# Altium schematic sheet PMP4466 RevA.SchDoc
size 431 x 279 mm; Date: Not shown in title block; ApprovedBy: Not shown in title block; CheckedBy: Not shown in title block; Author: Not shown in title block; CompanyName: Not shown in title block; Engineer: Jackyzhang; Organization: Not shown in title block; Address1: Not shown in title block; Address2: Not shown in title block; Address3: Not shown in title block; Address4: Not shown in title block; DocumentNumber: 1; Revision: A; SheetNumber: 1; SheetTotal: 1; PageSetup: Record=PageOptions¦CenterHorizontal=True¦CenterVertical=True¦PrintScale=1.00¦XCorrection=1.00¦YCorrection=1.00¦PrintKind=0¦BorderSize=5000000¦LeftOffset=0¦BottomOffset=0¦Orientation=2¦PaperLength=1000¦PaperWidth=1000¦Scale=100¦PaperSource=15¦PrintQuality=600¦MediaType=1¦DitherType=10¦PaperKind=Letter¦PrintScaleMode=1
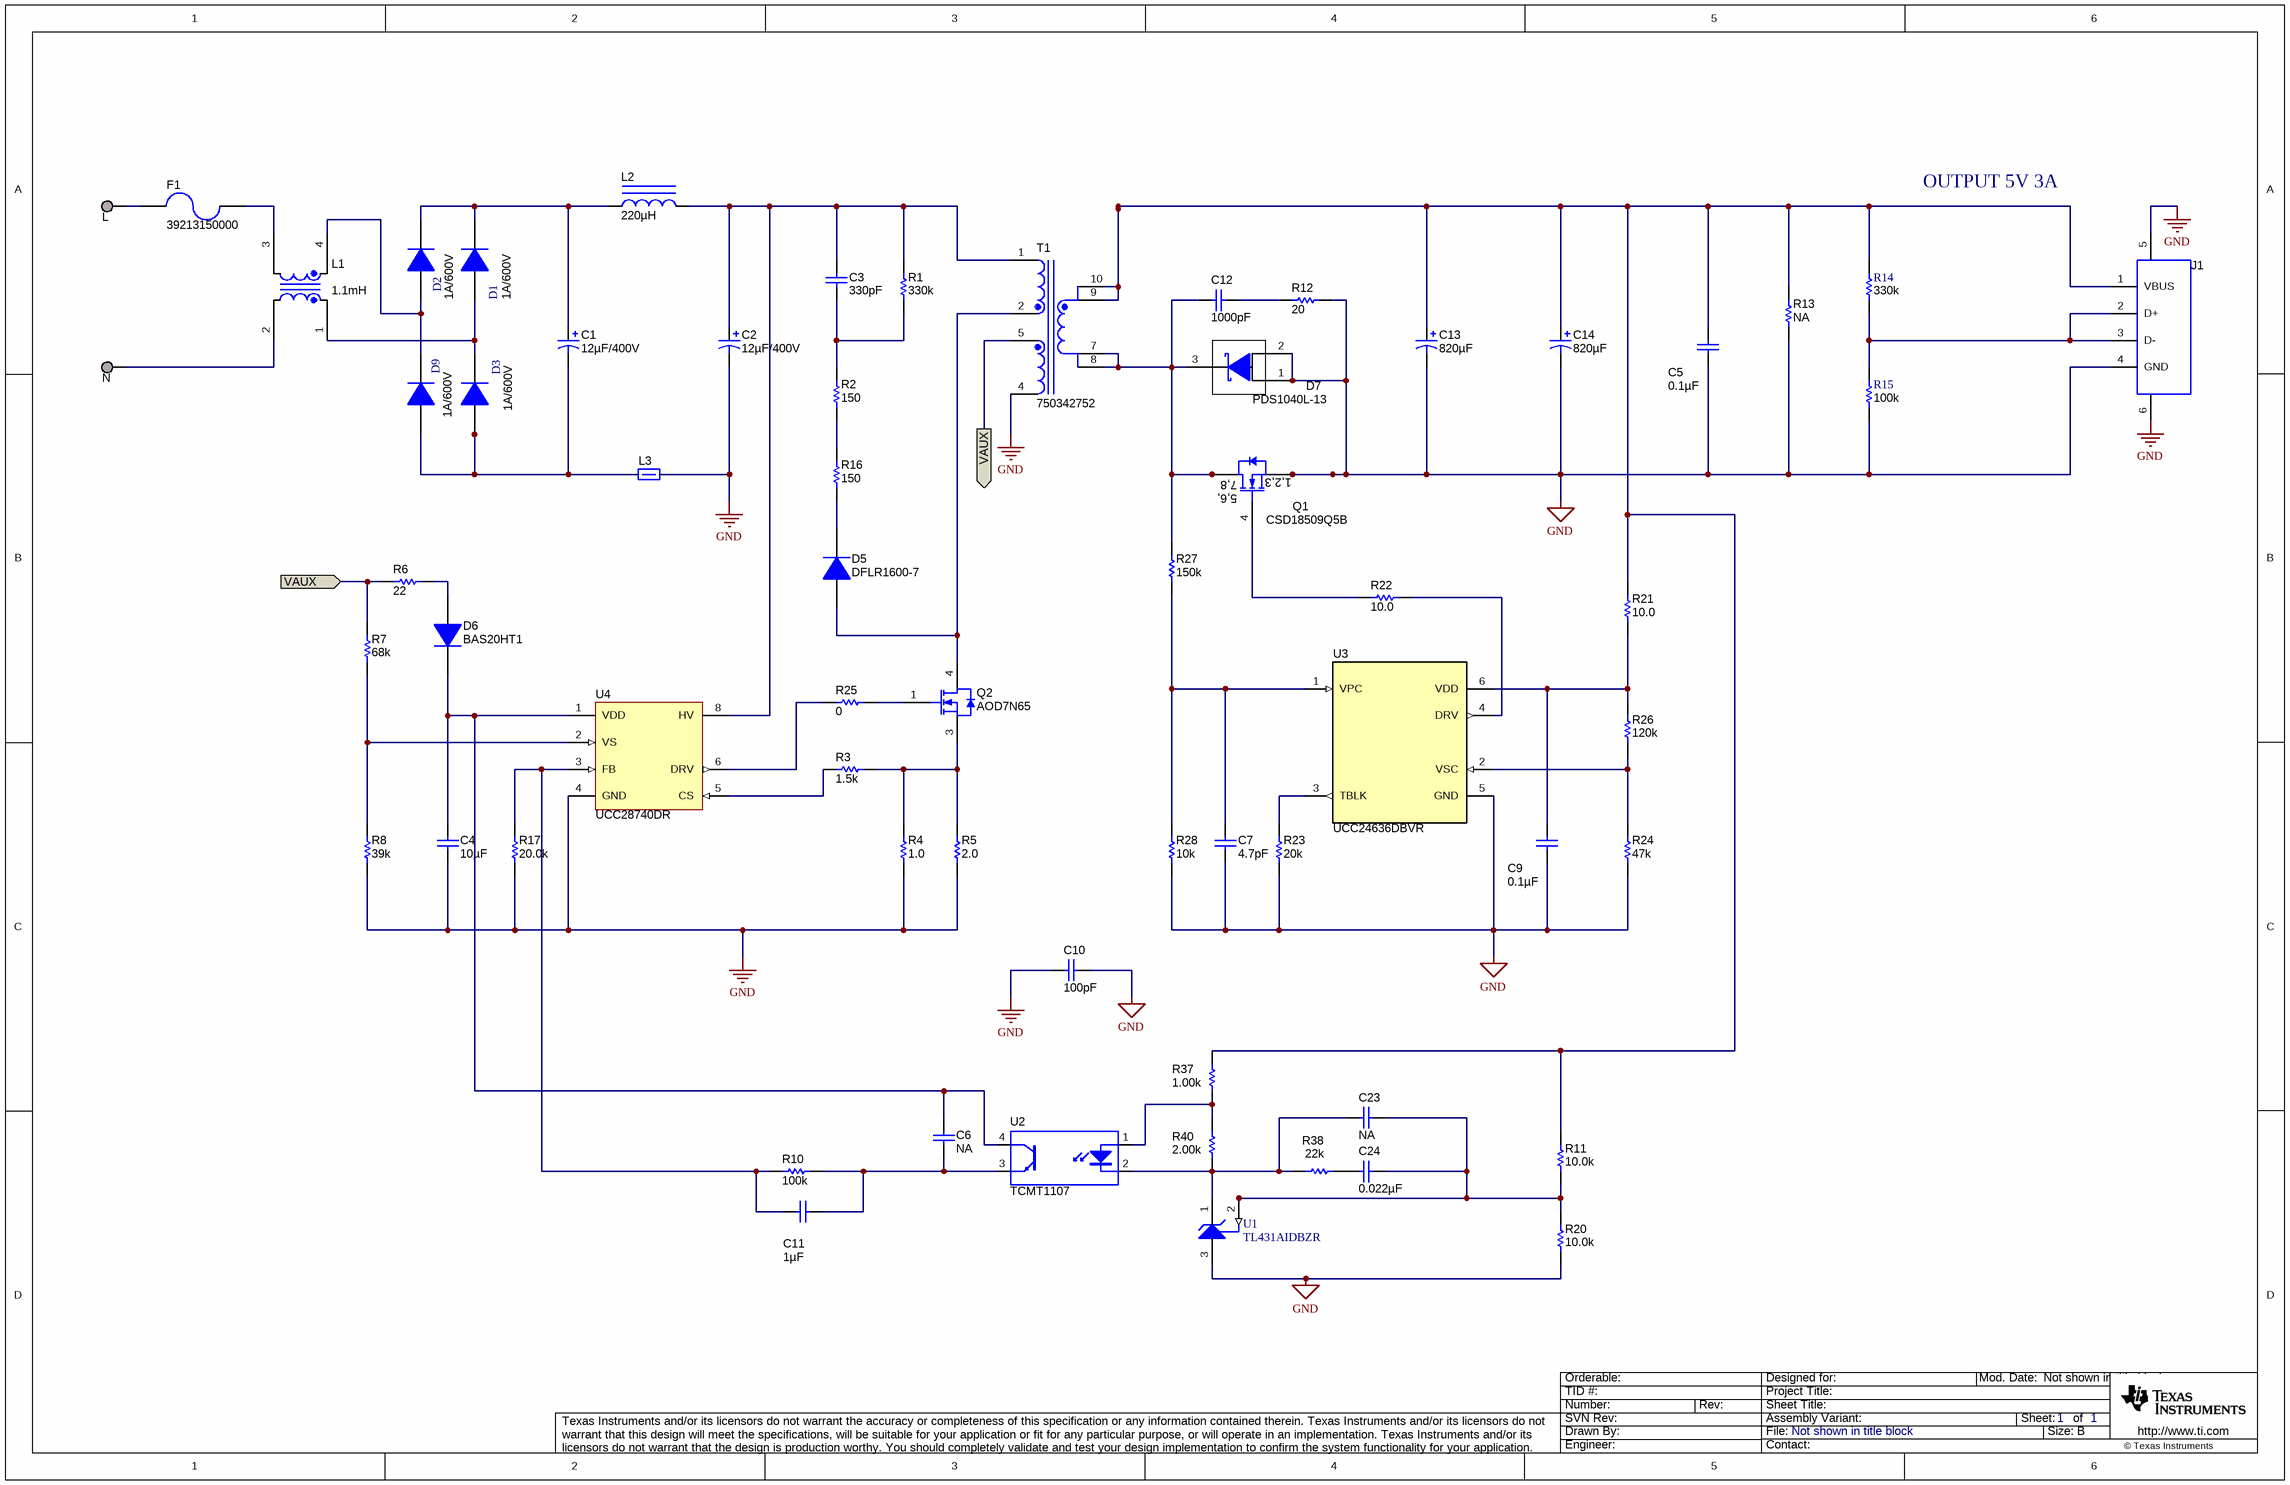
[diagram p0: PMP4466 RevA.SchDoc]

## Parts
C1  ValueDisplayed: 12µF/400V  [CAPPR5-10X20]  (hidden comment: EEUED2G100)
C2  ValueDisplayed: 12µF/400V  [CAPPR5-10X20]  (hidden comment: EEUED2G100)
C3  ValueDisplayed: 330pF  [1206]  (hidden comment: GRM31A5C2J331JW01D)
C4  ValueDisplayed: 10µF  [1206_190]  (hidden comment: GMK316AB7106KL-TR)
C5  ValueDisplayed: 0.1µF  [0603]  (hidden comment: C1608X7R1E104K)
C6  ValueDisplayed: NA  [0603]  (hidden comment: C0603X223K5RACTU)
C7  ValueDisplayed: 4.7pF  [0603]  (hidden comment: 06035A150JAT2A)
C9  ValueDisplayed: 0.1µF  [0603]  (hidden comment: C1608X7R1E104K)
C10  ValueDisplayed: 100pF  [CAPRD1000W60D1000H1400]  (hidden comment: DE1B3KX101K)
C11  ValueDisplayed: 1µF  [0603_095]  (hidden comment: C0603C105K3RACTU)
C12  ValueDisplayed: 1000pF  [0603]  (hidden comment: 06035A102KAT2A)
C13  ValueDisplayed: 820µF  [CAPSMT_62_J80]  (hidden comment: APXE6R3ARA821MJ80G)
C14  ValueDisplayed: 820µF  [CAPSMT_62_J80]  (hidden comment: APXE6R3ARA821MJ80G)
C23  ValueDisplayed: NA  [0603]  (hidden comment: C0603X223K5RACTU)
C24  ValueDisplayed: 0.022µF  [0603]  (hidden comment: C0603X223K5RACTU)
D1  1A/600V  [powerDI123]
D2  1A/600V  [powerDI123]
D3  1A/600V  [powerDI123]
D5  DFLR1600-7  [powerDI123]
D6  BAS20HT1  [sod-323]
D7  PDS1040L-13  [PowerDI5]
D9  1A/600V  [powerDI123]
F1  39213150000  [FUSE_392]
J1  896-43-004-00-000000  [USB-BYDAAA]  (value not drawn)
L  TESTPOINT  [Keystone_5019]  (value not drawn)  (no BOM)
L1  ValueDisplayed: 1.1mH  [IND_RLTI-1081]  (hidden comment: 131205000043)
L2  ValueDisplayed: 220µH  [WE-TI_5075]  (hidden comment: 7447462221)
L3  HF70ACC322513  [1206]  (value not drawn)
N  TESTPOINT  [Keystone_5019]  (value not drawn)  (no BOM)
Q1  CSD18509Q5B  [TRANS_NexFET_Q5B]
Q2  AOD7N65  [DPAK]
R1  ValueDisplayed: 330k  [1206]  (hidden comment: CRCW1206330KJNEA)
R2  ValueDisplayed: 150  [1206]  (hidden comment: CRCW1206150RJNEA)
R3  ValueDisplayed: 1.5k  [0603]  (hidden comment: CRCW06031K50JNEA)
R4  ValueDisplayed: 1.0  [1206]  (hidden comment: CRCW12061R00JNEA)
R5  ValueDisplayed: 2.0  [1206]  (hidden comment: CRCW12062R00JNEA)
R6  ValueDisplayed: 22  [0603]  (hidden comment: CRCW060322R0JNEA)
R7  ValueDisplayed: 68k  [0603]  (hidden comment: CRCW060368K0JNEA)
R8  ValueDisplayed: 39k  [0603]  (hidden comment: CRCW060339K0JNEA)
R10  ValueDisplayed: 100k  [0603]  (hidden comment: CRCW0603100KFKEA)
R11  ValueDisplayed: 10.0k  [0603]  (hidden comment: CRCW060310K0FKEA)
R12  ValueDisplayed: 20  [0805_HV]  (hidden comment: CRCW080520R0JNEA)
R13  ValueDisplayed: NA  [0603]  (hidden comment: Res2)
R14  ValueDisplayed: 330k  [0603]  (hidden comment: RC0603FR-07330KL)
R15  ValueDisplayed: 100k  [0603]  (hidden comment: RC0603FR-07100KL)
R16  ValueDisplayed: 150  [1206]  (hidden comment: CRCW1206150RJNEA)
R17  ValueDisplayed: 20.0k  [0603]  (hidden comment: CRCW060320K0FKEA)
R20  ValueDisplayed: 10.0k  [0603]  (hidden comment: CRCW060310K0FKEA)
R21  ValueDisplayed: 10.0  [0603]  (hidden comment: CRCW060310R0FKEA)
R22  ValueDisplayed: 10.0  [0603]  (hidden comment: CRCW060310R0FKEA)
R23  ValueDisplayed: 20k  [0603]  (hidden comment: CRCW060313K0JNEA)
R24  ValueDisplayed: 47k  [0603]  (hidden comment: CRCW060347K0JNEA)
R25  ValueDisplayed: 0  [0603]  (hidden comment: CRCW06030000Z0EA)
R26  ValueDisplayed: 120k  [0603]  (hidden comment: CRCW060391K0JNEA)
R27  ValueDisplayed: 150k  [0603]  (hidden comment: CRCW0603150KFKEA)
R28  ValueDisplayed: 10k  [0603]  (hidden comment: CRCW060310K0JNEA)
R37  ValueDisplayed: 1.00k  [0603]  (hidden comment: CRCW06031K00FKEA)
R38  ValueDisplayed: 22k  [0603]  (hidden comment: CRCW060322K0JNEA)
R40  ValueDisplayed: 2.00k  [0603]  (hidden comment: CRCW06032K00FKEA)
T1  750342752  [Wurth_750342752]
U1  TL431AIDBZR  [DBZ0003A_N]
U2  TCMT1107  [SOP-4]
U3  UCC24636DBVR  [DBV0006A_N]
U4  UCC28740DR  [D0007A_N]

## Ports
VAUX (in), VAUX (out)

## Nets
GND: C2.2(-) C4.2 C5.2 C7.2 C9.2 C10.1 C10.2 C13.2(-) C14.2(-) D7.1(A) D7.2(A) J1.4(GND) J1.5(Shield) J1.6(Shield) L3.2 Q1.1(S) Q1.2(S) Q1.3(S) R4.1 R5.1 R8.1 R12.2 R13.1 R15.1 R17.1 R20.1 R23.1 R24.1 R28.1 T1.4 U1.3(ANODE) U3.5(GND) U4.4(GND)
VAUX: R6.2 R7.2 T1.5 ; port VAUX
NetC1_1: C1.1(+) D1.1(K) D2.1(K) L2.1
NetC1_2: C1.2(-) D3.2(A) D9.2(A) L3.1
NetC2_1: C2.1(+) C3.1 L2.2 R1.2 T1.1 U4.8(HV)
NetC3_2: C3.2 R1.1 R2.2
NetC4_1: C4.1 C6.1 D6.1(K) U2.4(C) U4.1(VDD)
NetC5_1: C5.1 C13.1(+) C14.1(+) J1.1(VBUS) R11.2 R13.2 R14.2 R21.2 R37.2 T1.9 T1.10
NetC6_2: C6.2 C11.1 R10.2 U2.3(E)
NetC7_1: C7.1 R27.1 R28.2 U3.1(VPC)
NetC9_1: C9.1 R21.1 R26.2 U3.6(VDD)
NetC11_2: C11.2 R10.1 R17.2 U4.3(FB)
NetC12_1: C12.1 R12.1
NetC12_2: C12.2 D7.3(K) Q1.5(D) Q1.6(D) Q1.7(D) Q1.8(D) R27.2 T1.7 T1.8
NetC23_1: C23.1 C24.1 R11.1 R20.2 U1.2(REF)
NetC23_2: C23.2 R38.1 R40.1 U1.1(CATHODE) U2.2(K)
NetC24_2: C24.2 R38.2
NetD1_2: D1.2(A) D3.1(K) L1.1
NetD2_2: D2.2(A) D9.1(K) L1.4
NetD5_1: D5.1(K) R16.1
NetD5_2: D5.2(A) Q2.4(D) T1.2
NetD6_2: D6.2(A) R6.1
NetF1_1: F1.1 L1.3
NetF1_2: F1.2 L.1
NetJ1_2: J1.2(D+) J1.3(D-) R14.1 R15.2
NetL1_2: L1.2 N.1
NetQ1_4: Q1.4(G) R22.1
NetQ2_1: Q2.1(G) R25.2
NetQ2_3: Q2.3(S) R3.2 R4.2 R5.2
NetR2_1: R2.1 R16.2
NetR3_1: R3.1 U4.5(CS)
NetR7_1: R7.1 R8.2 U4.2(VS)
NetR22_2: R22.2 U3.4(DRV)
NetR23_2: R23.2 U3.3(TBLK)
NetR24_2: R24.2 R26.1 U3.2(VSC)
NetR25_1: R25.1 U4.6(DRV)
NetR37_1: R37.1 R40.2 U2.1(A)

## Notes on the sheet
- OUTPUT 5V 3A

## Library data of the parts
C1 C2 = EEUED2G100: CAP, AL, 10 µF, 400 V, +/- 20%, 2.864788 ohm, TH; Manufacturer: Panasonic; Polarized: Y; CompType: Capacitor; Value: 12uF; U/M: EA; Cap_F: 0.00001; Tolerance_%: 20; VDC_V: 400; Value2: 400V; IRMS_A: 0.3; TaMin_C: -25; TaMax_C: 105
C3 = GRM31A5C2J331JW01D: CAP, CERM, 330 pF, 630 V, +/- 5%, C0G/NP0, 1206; Manufacturer: MuRata; Polarized: N; CompType: Capacitor; Value: 330pF; U/M: EA; Cap_F: 0.00000000033; Tolerance_%: 5; Value1: Unknown; VDC_V: 630; Value2: 630V; TaMin_C: -55; TaMax_C: 125
C4 = GMK316AB7106KL-TR: CAP, CERM, 10 µF, 35 V, +/- 10%, X7R, 1206_190; Manufacturer: Taiyo Yuden; Polarized: N; CompType: Capacitor; Value: 10uF; U/M: EA; Cap_F: 0.00001; Tolerance_%: 10; Value1: Unknown; VDC_V: 35; Value2: 35V; TaMin_C: -55; TaMax_C: 125; Cap_Case: 1206
C5 C9 = C1608X7R1E104K: CAP, CERM, 0.1 µF, 25 V, +/- 10%, X7R, 0603; Manufacturer: TDK; Polarized: N; CompType: Capacitor; Value: 0.1uF; U/M: EA; Cap_F: 0.0000001; Tolerance_%: 10; ESR_ohm: 0.017; Value1: 0.017 ohm; VDC_V: 25; Value2: 25V; TaMin_C: -55; TaMax_C: 125
C6 C23 C24 = C0603X223K5RACTU: CAP, CERM, 0.022 µF, 50 V, +/- 10%, X7R, 0603; Manufacturer: Kemet; Polarized: N; CompType: Capacitor; Value: 0.022uF; U/M: EA; Cap_F: 0.000000022; Tolerance_%: 10; Value1: Unknown; VDC_V: 50; Value2: 50V; TaMin_C: -55; TaMax_C: 125
C7 = 06035A150JAT2A: CAP, CERM, 15 pF, 50 V, +/- 5%, C0G/NP0, 0603; Manufacturer: AVX; Polarized: N; CompType: Capacitor; Value: 15pF; U/M: EA; Cap_F: 0.000000000015; Tolerance_%: 5; ESR_ohm: 0.32; Value1: 0.32 ohm; VDC_V: 50; Value2: 50V; TaMin_C: -55; TaMax_C: 125
C10 = DE1E3KX222MA5BA01: CAP, CERM, 100 pF, 250 V, +/- 20%, E, Disc 10x8mm; Manufacturer: MuRata; Polarized: N; CompType: Capacitor; Value: 100pF; U/M: EA; Cap_F: 0.0000000022; Tolerance_%: 20; Value1: Unknown; VDC_V: 250; Value2: 250V; TaMin_C: -25; TaMax_C: 85
C11 = C0603C105K3RACTU: CAP, CERM, 1 µF, 25 V, +/- 10%, X7R, 0603_095; Manufacturer: Kemet; Polarized: N; CompType: Capacitor; Value: 1uF; U/M: EA; Cap_F: 0.000001; Tolerance_%: 10; Value1: Unknown; VDC_V: 25; Value2: 25V; TaMin_C: -55; TaMax_C: 125; Cap_Case: 0603
C12 = 06035A102KAT2A: CAP, CERM, 1000 pF, 50 V, +/- 10%, C0G/NP0, 0603; Manufacturer: AVX; Polarized: N; CompType: Capacitor; Value: 1000pF; U/M: EA; Cap_F: 0.000000001; Tolerance_%: 10; ESR_ohm: 0.048; Value1: 0.048 ohm; VDC_V: 50; Value2: 50V; TaMin_C: -55; TaMax_C: 125
C13 C14 = APXE6R3ARA821MJ80G: CAP, AL, 820 µF, 6.3 V, +/- 20%, 0.014 ohm, SMD; Manufacturer: Chemi-Con; Polarized: Y; CompType: Capacitor; Value: 820uF; U/M: EA; Cap_F: 0.00082; Tolerance_%: 20; VDC_V: 6.3; Value2: 6.3V; ESR_ohm: 0.014; IRMS_A: 4.3; TaMin_C: -55; TaMax_C: 105; Cap_Case: J80; AEC Category: Q200
D1-D3 D9 = DFLR1600-7: Diode, Standard Recovery Rectifier, 600 V, 1 A, PowerDI123; Manufacturer: Diodes Inc.; U/M: EA; Vf_V: 1.1; Value: 600V; Value1: 1A; Value2: 1.1V; Io_A: 1; Vr_V: 600; TJmax_C: 150; AEC Category: Q101
D5 = DFLR1600-7: Diode, Standard Recovery Rectifier, 600 V, 1 A, PowerDI123; Manufacturer: Diodes Inc.; U/M: EA; Vf_V: 1.1; Value: 600V; Value1: 1A; Value2: 1.1V; Io_A: 1; Vr_V: 600; TJmax_C: 150
D6 = BAV20WS-TP: Diode, P-N, 150 V, 0.2 A, SOD-323; Manufacturer: ON Semiconductor; U/M: EA; Vf_V: 1.25; Value: 150V; Value1: 0.2A; Value2: 1.25V; Io_A: 0.2; Vr_V: 150
D7 = PDS1040L-13: Diode, Schottky, 40 V, 10 A, PowerDI5; Manufacturer: Diodes Inc.; U/M: EA; Vf_V: 0.49; Value: 40V; Value1: 10A; Value2: 0.49V; Io_A: 10; Vr_V: 40; TJmax_C: 150; RJC_CperW: 85
F1 = 39213150000: Fuse, 3.15 A, 250 V, TH; Manufacturer: Littelfuse; U/M: EA; OpeningTime_200%_max: 120; VDC_V: 250; Irating_A: 3.15; Vdrop: 0.08; Soldering_Wave_MaxTemp_C: 260; Soldering_Wave_MaxTime_s: 5
J1 = 896-43-004-00-000000: Connector, Receptacle, USB TYPE A, R/A, Top Mount SMT; Manufacturer: Mill-Max; SymbolCreator: a0412235; Pitch_mm: 2; Gender: Female; Shrouded: N; Row_Count: 1; ContactFinish: Gold; Voltage_V: 30
L N = 5019: Test Point, Miniature, SMT; Manufacturer: Keystone; CompType: Test Point Loop; U/M: EA
L1 = RLTI-1081: Coupled inductor, 1.1 mH, TH; Manufacturer: Dongguan Yuefeng; SymbolCreator: a0412235; Ind_H: 806.0E-6; DCR_ohm: 0.27; Tolerance_%: 25; Value: 1.1mH
L2 = 7447462221: Inductor, Unshielded Drum Core, Ferrite, 220 µH, 0.5 A, 0.96 ohm, TH; Manufacturer: Wurth Elektronik; Value: 220uH; Ind_H: 220.0E-6; Imax_A: 0.5; Irms: 0.5A @ 40C rise; Isat: 0.5A @ 10% inductance drop; DCR_ohm: 0.96; Value2: 0.5A; AEC Category: Q200
L3 = HZ1206E152R-10: Ferrite Bead, 950 ohm @ 100 MHz, 0.5 A, 1206; Manufacturer: TDK; Imax_A: 0.5; DCR_ohm: 0.3
Q1 = CSD18509Q5B: MOSFET, N-CH, 40 V, 38 A, SON 5x6mm; Manufacturer: Texas Instruments; Alternate Manufacturer: None; U/M: EA; ChType: N; Value: 40V; VdsMax_V: 40; Value1: 0.0017 ohm; Rdson45_ohm: 0.0017; Value2: 150 nC; QgTyp_nC: 150; Vgs_V: 20; IdsMax_A: 38
Q2 = AOD7N65: MOSFET, N-CH, 650 V, 7 A, DPAK; Manufacturer: AOS; Alternate Manufacturer: None; U/M: EA; ChType: N; Value: 650V; VdsMax_V: 650; Value1: ? ohm; Value2: 19.6 nC; QgTyp_nC: 19.6; Vgs_V: 30; IdsMax_A: 7
R1 = CRCW1206330KJNEA: RES, 330 k, 5%, 0.25 W, 1206; Manufacturer: Vishay-Dale; CompType: Resistor; Value: 330k; Res_ohm: 330000; Tolerance_%: 5; Power_W: 0.25; Value2: 0.25W; VDC_V: 200; TempCo: 200 ppm/C; EIA_Code: E24; U/M: EA
R2 R16 = CRCW1206150RJNEA: RES, 150, 5%, 0.25 W, 1206; Manufacturer: Vishay-Dale; CompType: Resistor; Value: 150; Value_Code: 150R; Tolerance_%: 5; Power_W: 0.25; Value2: 0.25W; VDC_V: 200; TempCo: 200 ppm/C; EIA_Code: E24; U/M: EA
R3 = CRCW06031K50JNEA: RES, 1.5 k, 5%, 0.1 W, 0603; Manufacturer: Vishay-Dale; CompType: Resistor; Value: 1.5k; Res_ohm: 1500; Value_Code: 1k50; Tolerance_%: 5; Power_W: 0.1; Value2: 0.1W; VDC_V: 75; TempCo: 200 ppm/C; EIA_Code: E24; U/M: EA
R4 = CRCW12061R00JNEA: RES, 1.0, 5%, 0.25 W, 1206; Manufacturer: Vishay-Dale; CompType: Resistor; Value: 1.0; Res_ohm: 1; Value_Code: 1R00; Tolerance_%: 5; Power_W: 0.25; Value2: 0.25W; VDC_V: 200; TempCo: 200 ppm/C; EIA_Code: E24; U/M: EA
R5 = CRCW12062R00JNEA: RES, 2.0, 5%, 0.25 W, 1206; Manufacturer: Vishay-Dale; CompType: Resistor; Value: 2.0; Res_ohm: 2; Value_Code: 2R00; Tolerance_%: 5; Power_W: 0.25; Value2: 0.25W; VDC_V: 200; TempCo: 200 ppm/C; EIA_Code: E24; U/M: EA
R6 = CRCW060322R0JNEA: RES, 22, 5%, 0.1 W, 0603; Manufacturer: Vishay-Dale; CompType: Resistor; Value: 22; Value_Code: 22R0; Tolerance_%: 5; Power_W: 0.1; Value2: 0.1W; VDC_V: 75; TempCo: 200 ppm/C; EIA_Code: E24; U/M: EA
R7 = CRCW060368K0JNEA: RES, 68 k, 5%, 0.1 W, 0603; Manufacturer: Vishay-Dale; CompType: Resistor; Value: 68k; Res_ohm: 68000; Value_Code: 68k0; Tolerance_%: 5; Power_W: 0.1; Value2: 0.1W; VDC_V: 75; TempCo: 200 ppm/C; EIA_Code: E24; U/M: EA
R8 = CRCW060339K0JNEA: RES, 39 k, 5%, 0.1 W, 0603; Manufacturer: Vishay-Dale; CompType: Resistor; Value: 39k; Res_ohm: 39000; Value_Code: 39k0; Tolerance_%: 5; Power_W: 0.1; Value2: 0.1W; VDC_V: 75; TempCo: 200 ppm/C; EIA_Code: E24; U/M: EA
R10 = CRCW0603100KFKEA: RES, 100 k, 1%, 0.1 W, 0603; Manufacturer: Vishay-Dale; CompType: Resistor; Value: 100k; Res_ohm: 100000; Tolerance_%: 1; Power_W: 0.1; Value2: 0.1W; VDC_V: 75; TempCo: 100 ppm/C; EIA_Code: E96; U/M: EA
R11 R20 = CRCW060310K0FKEA: RES, 10.0 k, 1%, 0.1 W, 0603; Manufacturer: Vishay-Dale; CompType: Resistor; Value: 10.0k; Res_ohm: 10000; Value_Code: 10k0; Tolerance_%: 1; Power_W: 0.1; Value2: 0.1W; VDC_V: 75; TempCo: 100 ppm/C; EIA_Code: E96; U/M: EA
R12 = CRCW080520R0JNEA: RES, 20, 5%, 0.125 W, 0805; Manufacturer: Vishay-Dale; CompType: Resistor; Value: 20; Value_Code: 20R0; Tolerance_%: 5; Power_W: 0.125; Value2: 0.125W; VDC_V: 150; TempCo: 200 ppm/C; EIA_Code: E24; U/M: EA
R13 = RC0603FR-071K3L: RES, 1.30 k, 1%, 0.1 W, 0603; Manufacturer: Yageo America; CompType: Resistor; Value: 1.30k; Res_ohm: 1300; Value_Code: 1k30; Tolerance_%: 1; Power_W: 0.1; Value2: 0.1W; VDC_V: 150; TempCo: 200 ppm/C; EIA_Code: E96; U/M: EA; AEC Category: Q200
R14 = RC0603FR-07330KL: RES, 330 k, 1%, 0.1 W, 0603; Manufacturer: Yageo America; Value: 330k; CompType: Resistor; Res_ohm: 330000; Tolerance_%: 1; Power_W: 0.1; Value2: 0.1W; VDC_V: 150; TempCo: 200 ppm/C; U/M: EA; AEC Category: Q200
R15 = RC0603FR-07100KL: RES, 100 k, 1%, 0.1 W, 0603; Manufacturer: Yageo America; Value: 100k; CompType: Resistor; Res_ohm: 100000; Tolerance_%: 1; Power_W: 0.1; Value2: 0.1W; VDC_V: 150; TempCo: 200 ppm/C; EIA_Code: E96; U/M: EA; AEC Category: Q200
R17 = CRCW060320K0FKEA: RES, 20.0 k, 1%, 0.1 W, 0603; Manufacturer: Vishay-Dale; CompType: Resistor; Value: 20.0k; Res_ohm: 20000; Value_Code: 20k0; Tolerance_%: 1; Power_W: 0.1; Value2: 0.1W; VDC_V: 75; TempCo: 100 ppm/C; EIA_Code: E96; U/M: EA
R21 R22 = CRCW060310R0FKEA: RES, 10.0, 1%, 0.1 W, 0603; Manufacturer: Vishay-Dale; CompType: Resistor; Value: 10.0; Res_ohm: 10; Value_Code: 10R0; Tolerance_%: 1; Power_W: 0.1; Value2: 0.1W; VDC_V: 75; TempCo: 100 ppm/C; EIA_Code: E96; U/M: EA; AEC Category: Q200
R23 = CRCW060313K0JNEA: RES, 13 k, 5%, 0.1 W, 0603; Manufacturer: Vishay-Dale; CompType: Resistor; Value: 13k; Res_ohm: 13000; Value_Code: 13k0; Tolerance_%: 5; Power_W: 0.1; Value2: 0.1W; VDC_V: 75; TempCo: 200 ppm/C; EIA_Code: E24; U/M: EA
R24 = CRCW060347K0JNEA: RES, 47 k, 5%, 0.1 W, 0603; Manufacturer: Vishay-Dale; CompType: Resistor; Value: 47k; Res_ohm: 47000; Value_Code: 47k0; Tolerance_%: 5; Power_W: 0.1; Value2: 0.1W; VDC_V: 75; TempCo: 200 ppm/C; EIA_Code: E24; U/M: EA
R25 = CRCW06030000Z0EA: RES, 0, 5%, 0.1 W, 0603; Manufacturer: Vishay-Dale; CompType: Resistor; Value: 0; Value_Code: 0000; Tolerance_%: 5; Power_W: 0.1; Value2: 0.1W; VDC_V: 75; TempCo: 200 ppm/C; EIA_Code: E24; U/M: EA
R26 = CRCW060391K0JNEA: RES, 91 k, 5%, 0.1 W, 0603; Manufacturer: Vishay-Dale; CompType: Resistor; Value: 91k; Res_ohm: 91000; Value_Code: 91k0; Tolerance_%: 5; Power_W: 0.1; Value2: 0.1W; VDC_V: 75; TempCo: 200 ppm/C; EIA_Code: E24; U/M: EA
R27 = CRCW0603150KFKEA: RES, 150 k, 1%, 0.1 W, 0603; Manufacturer: Vishay-Dale; CompType: Resistor; Value: 150k; Res_ohm: 150000; Tolerance_%: 1; Power_W: 0.1; Value2: 0.1W; VDC_V: 75; TempCo: 100 ppm/C; EIA_Code: E96; U/M: EA
R28 = CRCW060310K0JNEA: RES, 10 k, 5%, 0.1 W, 0603; Manufacturer: Vishay-Dale; CompType: Resistor; Value: 10k; Res_ohm: 10000; Value_Code: 10k0; Tolerance_%: 5; Power_W: 0.1; Value2: 0.1W; VDC_V: 75; TempCo: 200 ppm/C; EIA_Code: E24; U/M: EA
R37 = CRCW06031K00FKEA: RES, 1.00 k, 1%, 0.1 W, 0603; Manufacturer: Vishay-Dale; CompType: Resistor; Value: 1.00k; Res_ohm: 1000; Value_Code: 1k00; Tolerance_%: 1; Power_W: 0.1; Value2: 0.1W; VDC_V: 75; TempCo: 100 ppm/C; EIA_Code: E96; U/M: EA
R38 = CRCW060322K0JNEA: RES, 22 k, 5%, 0.1 W, 0603; Manufacturer: Vishay-Dale; CompType: Resistor; Value: 22k; Res_ohm: 22000; Value_Code: 22k0; Tolerance_%: 5; Power_W: 0.1; Value2: 0.1W; VDC_V: 75; TempCo: 200 ppm/C; EIA_Code: E24; U/M: EA
R40 = CRCW06032K00FKEA: RES, 2.00 k, 1%, 0.1 W, 0603; Manufacturer: Vishay-Dale; CompType: Resistor; Value: 2.00k; Res_ohm: 2000; Value_Code: 2k00; Tolerance_%: 1; Power_W: 0.1; Value2: 0.1W; VDC_V: 75; TempCo: 100 ppm/C; EIA_Code: E96; U/M: EA
T1 = 750342752: Transformer, 515 uH, TH; Manufacturer: Wurth Elektronik; SymbolCreator: Altium; DCR_Ohm: 0.66; Value: 515 uH; LeakageL: 20 uH; U/M: EA
U1 = TL431AIDBZR: Adjustable Precision Shunt Regulator, 34 ppm / degC, 100 mA, -40 to 85 degC, 3-pin SOT-23 (DBZ), Green (RoHS & no Sb/Br); Manufacturer: Texas Instruments; Alternate Manufacturer: None; Alternate PartNumber: Equivalent; Initial Accuracy @ 25/deg C(%): 1; Iout/Iz(Max)(mA): 100; Min Iz for Regulation(uA): 600; Rating: Catalog; SubFamily: Shunt Voltage Reference; Temp Coeff(Max)(ppm/ degree C): 92; Temp Coeff(Typ)(ppm/ degree C): 34; VO Adj(Max)(V): 36; VO Adj(Min)(V): 2.495
U2 = TCMT1107: Optocoupler, 3.75 kV, 80-160% CTR, SMD-4; Manufacturer: Vishay-Semiconductor; CTR_Min: 80% @ 5mA; CTR_Max: 160% @ 5mA; Voltage_Isolation_Vrms: 3750; tr_typ: 4us; tf_typ: 4.7us; U/M: EA
U3 = UCC24636DBVR: SYNCRONOUS RECTIFIER CONTROLLER WITH LOW POWER STANDBY, DBV0006A; Alternate PartNumber: UCC24636DBVT; Manufacturer: Texas Instruments; SymbolCreator: a0411947; CompType: IC; U/M: EA
U4 = UCC28740DR: Constant-Voltage, Constant-Current Flyback Controller Using Opto-Coupler Feedback, D0007A; Manufacturer: Texas Instruments; SymbolCreator: a0412235; CompType: IC; U/M: EA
